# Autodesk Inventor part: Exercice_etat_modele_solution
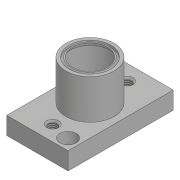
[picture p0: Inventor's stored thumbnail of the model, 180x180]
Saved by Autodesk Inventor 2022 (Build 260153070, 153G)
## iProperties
Created: 2018-06
Part Number: Exercice_etat_modele_solution
Material: Aluminium 6061
Document SubType Name: Modeling
Designer: Fabian Perrée
Density: 2.7 g/cm^3
Appearance: Gris clair
Mass: 26.5554 g
Surface Area: 66.9581 cm^2
Volume: 9.83534 cm^3
Author: Fabian Perrée
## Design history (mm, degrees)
sketch "Esquisse1"
  geometry: L1 (-14, 24)-(14, 24); L2 (14, 24)-(14, -24); L3 (14, -24)-(-14, -24); L4 (-14, -24)-(-14, 24); L5 (-14, 24)-(14, -24); L6 (14, 24)-(-14, -24); 1 further point
  constraints: 12 end point, 2 midpoint, 2 parallel, 1 horizontal, 1 perpendicular
  dimensions: "d0" = 28 distance of L2.end L3.end; "d1" = 48 distance of L1.end L2.end
extrude "Extrusion1" new body sketch "Esquisse1" distance "d2" = 8; taper "d3" = 0 deg
sketch "Esquisse2"
  geometry: L1 (0, 0)-(8, 0); L2 (8, -24)-(8, 24) reference; L3 (26, -11)-(26, -9.5); L4 (26, -9.5)-(25, -9.5); L5 (25, -9.5)-(26, -8.5); L6 (26, -8)-(24.268, -9); L7 (24.268, -9)-(8, -9); L8 (8, -9)-(8, -11); L9 (26, -11)-(8, -11); L10 (26, -8.5)-(26, -8); L11 (8, -9)-(2.5, -9); L12 (2.5, -9)-(2.5, -11.5); L13 (2.5, -11.5)-(0, -11.5); L14 (0, 24)-(0, -24) reference; L15 (0, -11.5)-(0, 0); L16 (8, -9)-(8, 0); L17 (8, 0)-(26, 0)
  constraints: 30 end point, 5 point on line, 4 horizontal, 4 perpendicular, 2 collinear, 2 vertical, 1 midpoint
  dimensions: "d4" = 18 distance from line of L2 L17.end; "d5" = 1.5 distance of L3.start L3.end; "d6" = 1 distance of L3.end L4.end; "d7" = 45 deg angle of L4 L5; "d8" = 150 deg angle of L7 L6; "d9" = 22 diameter of L9 L1; "d10" = 16 diameter of L6.start L1; "d11" = 18 diameter of L7 L1; "d12" = 23 diameter of L13 L1; "d13" = 18 diameter of L11 L1; "d14" = 2.5 distance of L12.end L13.end
revolve "Révolution1" stored, may be unused: angle "d15" = 90 deg
revolve "Révolution2" stored, may be unused: angle "d16" = 90 deg
sketch "Esquisse3"
  geometry: L1 (14, -24)-(14, 24) reference; L2 (-14, -24)-(14, -24) reference; L3 (-14, 24)-(-14, -24) reference; L4 (14, 24)-(-14, 24) reference; 3 further points
  dimensions: "d17" = 5 distance from line of L1 point (9, -19); "d18" = 5 distance from line of L2 point (9, -19); "d19" = 5 distance from line of L3 point (-9, 19); "d20" = 5 distance from line of L4 point (-9, 19)
hole "Perçage1" sketch "Esquisse3" at (-9, 19), (9, -19) diameter "d21" = 4.5; stored, may be unused: countersink angle "d25" = 90 deg, drill point angle "d27" = 118 deg; dims "d22" = 6, "d23" = 7.5, "d24" = 5, "d26" = 8
sketch "Esquisse4"
  geometry: L1 (-14, 24)-(-14, -24) reference; L2 (-14, -24)-(14, -24) reference; L3 (14, 24)-(-14, 24) reference; 3 further points
  dimensions: "d28" = 14 distance from line of L1 point (0, -17); "d29" = 7 distance from line of L2 point (0, -17); "d30" = 14 distance from line of L1 point (0, 17); "d31" = 7 distance from line of L3 point (0, 17)
hole "Perçage2" sketch "Esquisse4" at (0, -17), (0, 17) diameter "d32" = 4; stored, may be unused: countersink angle "d36" = 90 deg, drill point angle "d38" = 118 deg; dims "d33" = 10, "d34" = 5.5, "d35" = 5, "d37" = 14.2
sketch "Esquisse8"
  geometry: L1 (-14, 24)-(-14, -24); L2 (-14, -24)-(14, -24); L3 (14, 24)-(-14, 24); 3 further points
  constraints: 6 end point
  dimensions: "d59" = 14 distance from line of L1 point (0, -17); "d58" = 7 distance from line of L2 point (0, -17); "d57" = 14 distance from line of L1 point (0, 17); "d56" = 7 distance from line of L3 point (0, 17)
hole "Perçage3" sketch "Esquisse8" at (0, -17), (0, 17) diameter "d65" = 4.134; stored, may be unused: drill point angle "d60" = 118 deg, countersink angle "d61" = 90 deg; dims "d55" = 10, "d62" = 5, "d63" = 5.5, "d64" = 14.2
chamfer "Chanfrein2" distance "d51" = 0.5; stored, may be unused: second distance "d52" = 2, angle "d53" = 45 deg
fillet "Congé1" dims "d54" = 0.5
node "Solide1"
